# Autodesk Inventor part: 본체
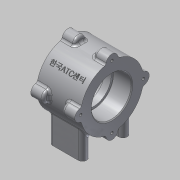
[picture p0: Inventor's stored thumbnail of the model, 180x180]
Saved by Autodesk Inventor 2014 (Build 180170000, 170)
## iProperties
Created: 2015-03
Part Number: 본체
Material: 알루미늄 6061
Document SubType Name: Modeling
Designer: MYHOME
Mass: 450.744 g
Surface Area: 332.348 cm^2
Volume: 166.326 cm^3
Density: 2.71 g/cm^3
Appearance: 알루미늄 - 평지
Author: MYHOME
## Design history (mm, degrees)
sketch "스케치2"
  geometry: C1 r 37 at (0, 0); 1 further point
  constraints: 1 centre point, 1 coincident
  dimensions: "d0" = 74 diameter of C1
extrude "돌출1" new body sketch "스케치2" stored distance "d1" = 52; taper "d2" = 0 deg
node "작업 평면1"
sketch "스케치3"
  geometry: L1 (-15, 24)-(15, 24); L2 (-15, 19)-(15, 19); L3 (15, 29)-(-15, 29); L4 (-15, -24)-(15, -24); L5 (-15, -29)-(15, -29); L6 (15, -19)-(-15, -19); A1 r 5 centre (-15, 24) between (-15, 29) and (-15, 19); A2 r 5 centre (15, 24) between (15, 19) and (15, 29); A3 r 5 centre (-15, -24) between (-15, -19) and (-15, -29); A4 r 5 centre (15, -24) between (15, -29) and (15, -19); 3 further points
  constraints: 16 end point, 8 point on circle, 8 tangent, 4 centre point, 3 parallel, 2 midpoint, 2 vertical alignment, 1 horizontal
  dimensions: "d4" = 40 dimension on A2 A1; "d5" = 40 dimension on A4 A3; "d6" = 10 distance between parallel lines of L3 L2; "d7" = 10 distance between parallel lines of L5 L6; "d8" = 24 distance of point (0, 0) point (0, -24); "d9" = 24 distance of point (0, 24) point (0, 0)
extrude "돌출2" join sketch "스케치3" stored distance "d10" = 52; taper "d11" = 0 deg
sketch "스케치4"
  geometry: C1 r 37 at (0, 0) reference; C2 r 23.5 at (0, 0)
  constraints: 1 centre point, 1 coincident
  dimensions: "d12" = 47 diameter of C2
extrude "돌출3" cut sketch "스케치4" distance "d13" = 22; taper "d14" = 0 deg
sketch "스케치5"
  geometry: C1 r 37 at (0, 0) reference; C2 r 23.5 at (0, 0)
  constraints: 1 centre point, 1 coincident
  dimensions: "d15" = 47 diameter of C2
extrude "돌출4" cut sketch "스케치5" distance "d16" = 22; taper "d17" = 0 deg
sketch "스케치6"
  geometry: C1 r 23.5 at (0, 0) reference; C2 r 21 at (0, 0)
  constraints: 1 centre point, 1 coincident
  dimensions: "d18" = 42 diameter of C2
extrude "돌출5" cut sketch "스케치6" distance "d19" = 22; taper "d20" = 0 deg
sketch "스케치7"
  geometry: C1 r 23.5 at (0, 0) reference; C2 r 7 at (-37, 0); C3 r 7 at (0, -37); C4 r 7 at (0, 37); C5 r 7 at (37, 0); A1 r 37 centre (0, 0) between (-37, 0) and (0, -37) reference
  constraints: 4 centre point, 4 point on circle, 2 horizontal alignment, 2 vertical alignment
  dimensions: "d21" = 14 diameter of C2; "d22" = 14 diameter of C3; "d23" = 14 diameter of C4; "d24" = 14 diameter of C5
extrude "돌출6" join sketch "스케치7" distance "d25" = 15; taper "d26" = 0 deg
sketch "스케치8"
  geometry: A1 r 7 centre (0, 37) between (6.969, 36.338) and (-6.969, 36.338) reference; A2 r 7 centre (-37, 0) between (-36.338, 6.969) and (-36.338, -6.969) reference; A3 r 7 centre (0, -37) between (-6.969, -36.338) and (6.969, -36.338) reference; A4 r 7 centre (37, 0) between (36.338, -6.969) and (36.338, 6.969) reference; 4 further points
  constraints: 4 coincident
hole "구멍1" sketch "스케치8" at (0, 37), (-37, 0), (0, -37), (37, 0) diameter "d27" = 3.242; stored, may be unused: countersink angle "d31" = 90 deg, drill point angle "d33" = 118 deg; dims "d28" = 8, "d29" = 4, "d30" = 2, "d32" = 11
chamfer "모따기1" distance "d34" = 1; stored, may be unused: second distance "d35" = 2, angle "d36" = 45 deg
fillet "모깎기1" dims "d37" = 0.3
fillet "모깎기2" dims "d38" = 3
fillet "모깎기3" dims "d39" = 3
fillet "모깎기4" dims "d40" = 3
sketch "스케치9"
  geometry: L1 (-15, -29)-(15, -29) reference; L2 (15, -19)-(-15, -19) reference; A1 r 5 centre (15, 24) between (15, 19) and (15, 29) reference; A2 r 5 centre (-15, 24) between (-15, 29) and (-15, 19) reference; A3 r 5 centre (-15, -24) between (-15, -19) and (-15, -29) reference; A4 r 5 centre (15, -24) between (15, -29) and (15, -19) reference; 5 further points
  constraints: 4 coincident
hole "구멍2" sketch "스케치9" at (-15, -24), (15, -24), (15, 24), (-15, 24) diameter "d41" = 4.134; stored, may be unused: countersink angle "d45" = 90 deg, drill point angle "d47" = 118 deg; dims "d42" = 6, "d43" = 4, "d44" = 2, "d46" = 8
sketch "스케치12"
  geometry: C1 r 21 at (0, 0) reference; 1 further point
sketch "스케치13"
  geometry: L1 (0, 0)-(-21, 0); L2 (0, 0)-(-26.163, 26.163); A1 r 37 centre (0, 0) between (-9.104, 35.863) and (-35.863, 9.104) reference; 3 further points
  constraints: 4 end point, 1 coincident, 1 horizontal, 1 horizontal alignment, 1 point on circle, 1 other
  dimensions: "d50" = 45 deg angle of L2 L1
node "작업 평면3"
sketch "스케치14"
  geometry: 2 further points
  constraints: 1 coincident, 1 other
feature "엠보싱2" sketch "스케치14" dims "d51" = 0.5, "d52" = 0
node "솔리드1"
mirror "대칭1"
other parameters: "d3" = -56
